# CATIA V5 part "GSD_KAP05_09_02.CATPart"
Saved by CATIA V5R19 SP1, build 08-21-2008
Part number: GSD_LAW_02
Definition: Beispielmodell für die Funktion Regel / Law.
Description: CATIA V5 Flächenmodellierung  Copyright (c) 2009 Maik Hertha IT Consultants
Bounding box of the stored display mesh (mm): x -91.557 to 88.482, y -20 to 133.916, z 10 to 46.567
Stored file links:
  \GSD_BUCH_UEBUNG\GSD_KAP05_09_02.CATPart
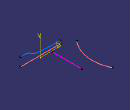
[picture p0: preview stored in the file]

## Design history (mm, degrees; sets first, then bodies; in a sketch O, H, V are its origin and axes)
AxisSystem1 "Absolute Axis System": origin (0, 0, 0), X (1, 0, 0), Y (0, 1, 0), Z (0, 0, 1)
Set1 "Regeldefinition.2"
  Plane1: type Equation, A 0, B 1, C 0, Length -20
  Point1: type OnPlane, Support Plane1, Direction (-1, 0, 0), H -20, V 10
  Sketch1 "Skizze.2" on Plane1, origin (20, -20, 10), H (-1, 0, 0), V (0, 0, 1)
    line L1 (-68.4823, 6.5665) -> (68.4823, 6.5665)
    point P1 (-68.4823, 6.5665)
    point P2 (68.4823, 6.5665)
    curve C1
    construction line L2 (68.4823, 19.0049) -> (68.4823, 58.7913)
    construction line L3 (-68.4823, 17.9499) -> (-68.4823, 57.9099)
    curve C2
    spline S1 through (-68.4823, 36.5665) (-63.2702, 36.5665) (-42.9377, 34.2489) (-30.0298, 27.6112) (8.5782, 18.344) (46.1902, 16.7566) (67.4914, 16.5665) (68.4823, 16.5665)
    construction line L4 (-68.4823, 36.5665) -> (-70.4679, 36.5665)
    point P7 (-68.4823, 36.5665)
    construction line L5 (68.4823, 16.5665) -> (118.6964, 16.5665)
    point P9 (68.4823, 16.5665)
    construction line L6 (0, 43.9966) -> (0, -35.5933)
    point P11 (0, 43.9966)
    construction line L7 (81.2681, 0) -> (-86.0419, 0)
    point P13 (81.2681, 0)
    point P15 (-68.4823, 36.5665)
    point P16 (68.4823, 16.5665)
    point P19 (67.4914, 16.5665)
    point P20 (-63.2702, 36.5665)
    distance L3 L2 = 136.9647
    distance L1 L4 = 30
    distance L1 L5 = 10
    horizontal: L1 H, L4 H, L5 H, L7 H
    vertical: L2 V, L3 V, L6 V
    coincidence: P1 L3, P2 L2, P15 L3, P16 L2, P15 P7, P16 P9, P11 V, P13 H, P19 L5, P20 L4
    tangency: S1 L5, L4 S1
    symmetry: L3 L2 L6
    fix: L1
Set2 "Regel anwenden.2"
  Plane2: type Equation, A 0, B 0, C 1, Length 10
  Plane3: type Equation, A 0, B 1, C 0, Length 10
  Point2: type OnSurface, Support Plane2, Direction (-0.7429, 0.6694, 0), Length 50
  Sketch2 "Skizze.4" on Plane2, origin (-37.146, 33.469, 10), H (0, 1, 0), V (-1, 0, 0)
    spline S1 through (-39.5527, 54.4113) (21.9865, 25.5539) (100.4474, 36.6941)
    curve C1
    line L1 (-49.2317, -19.4364) -> (51.0183, -19.4364)
    curve C2
    length L1 = 100.25
    horizontal: L1 H
Body1 (main body)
